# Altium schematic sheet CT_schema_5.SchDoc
size 578 x 363 mm
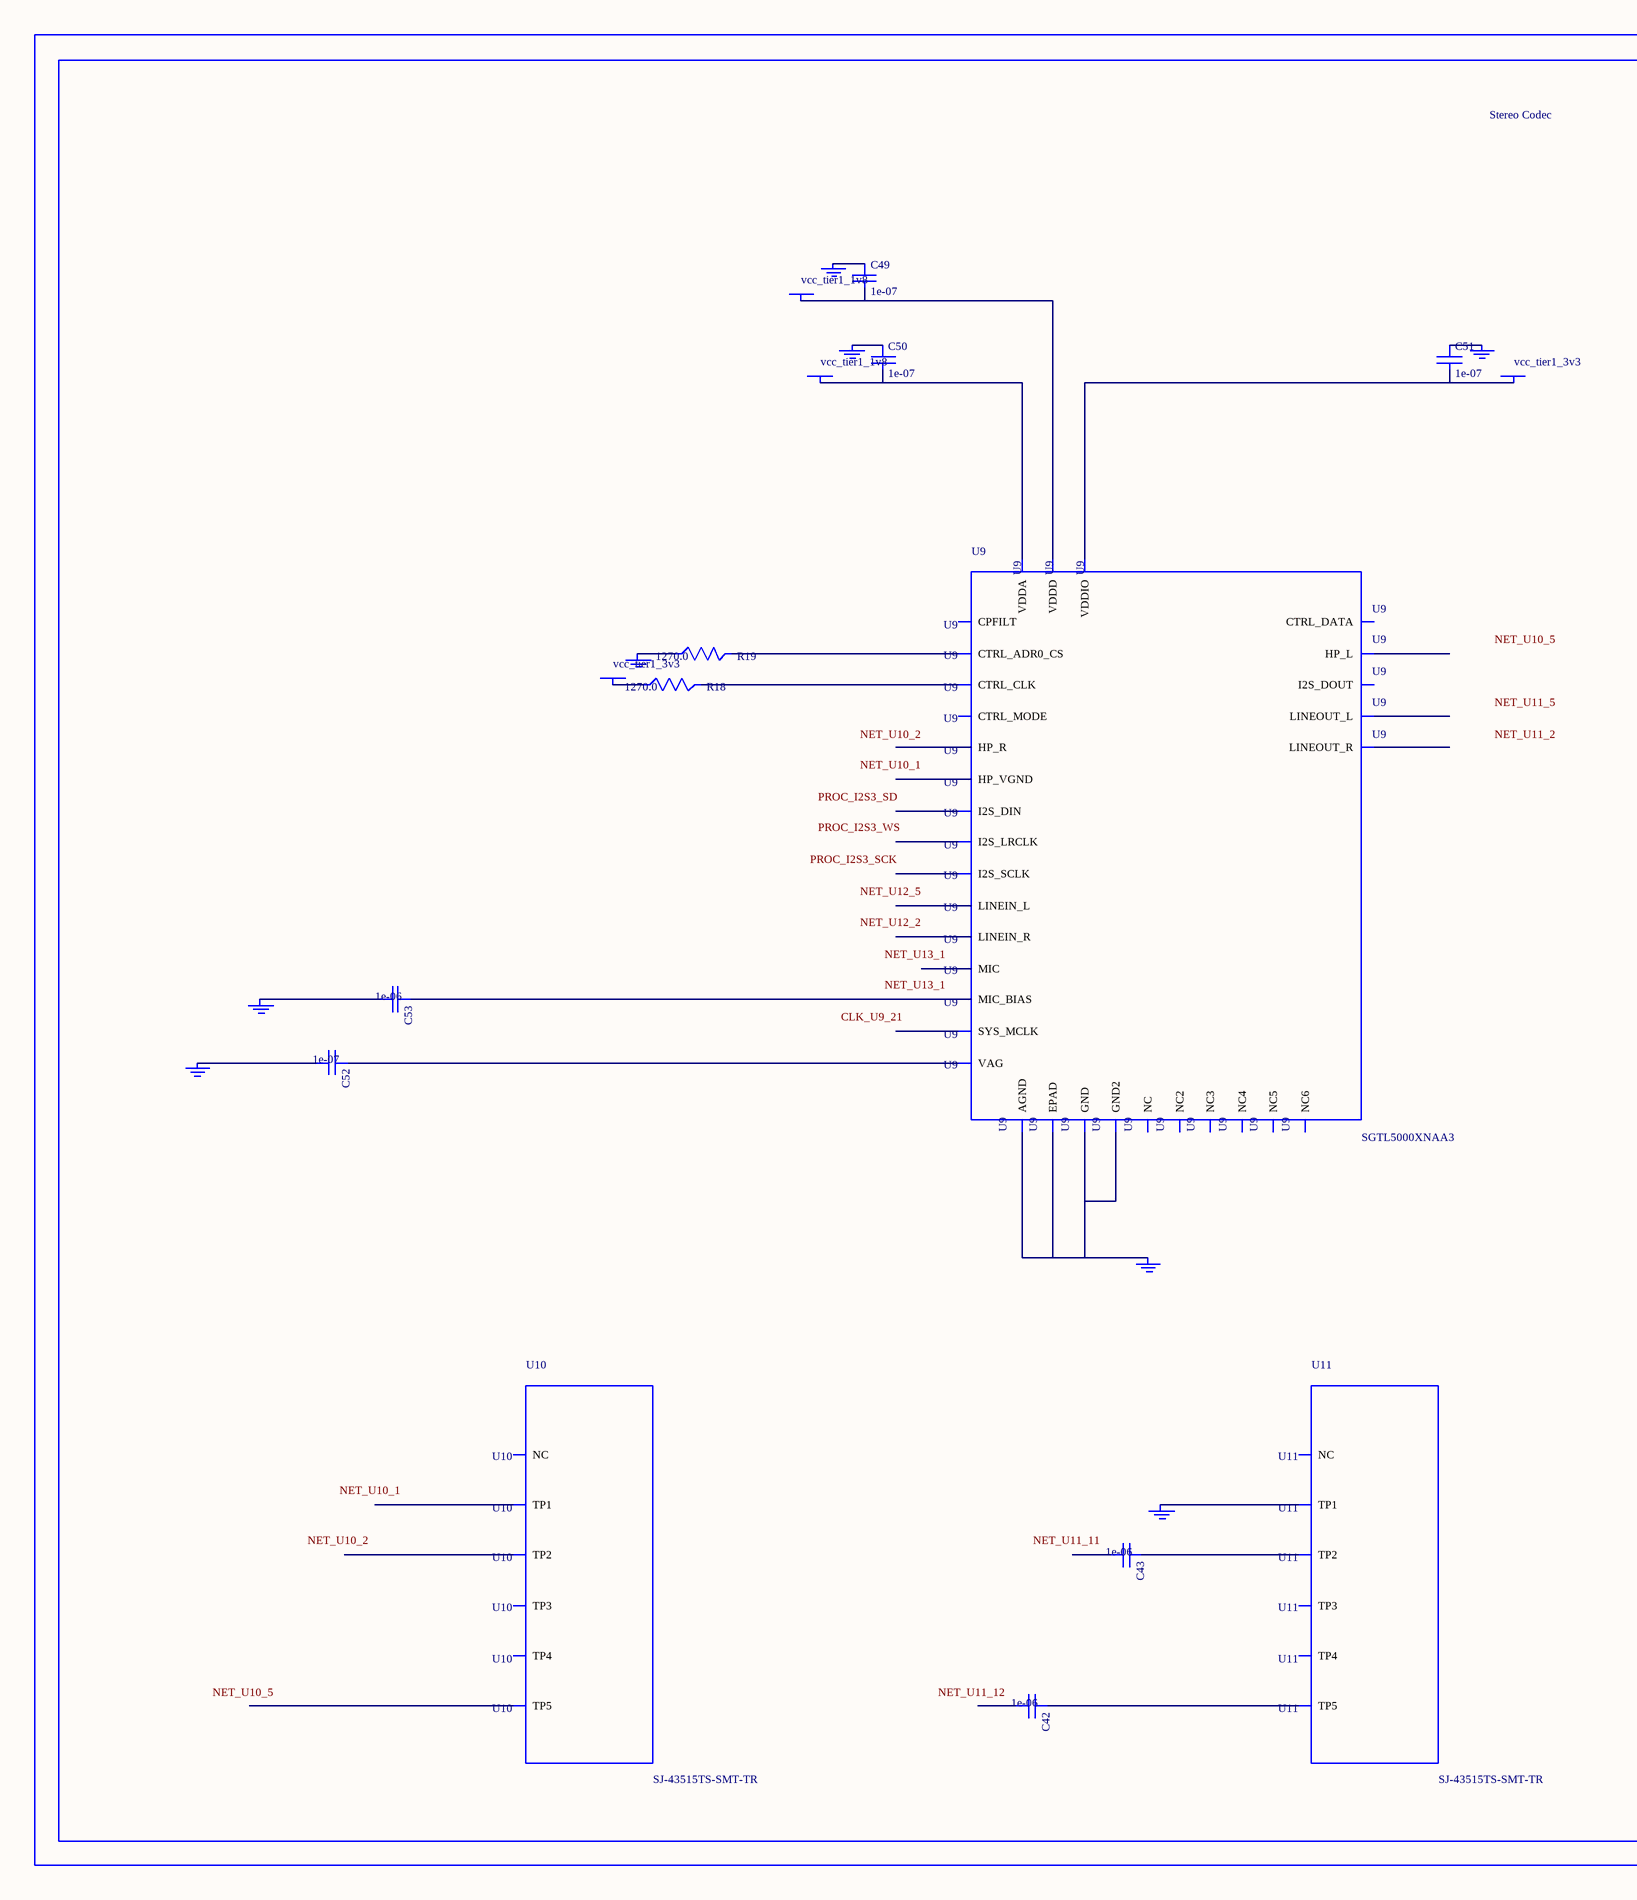
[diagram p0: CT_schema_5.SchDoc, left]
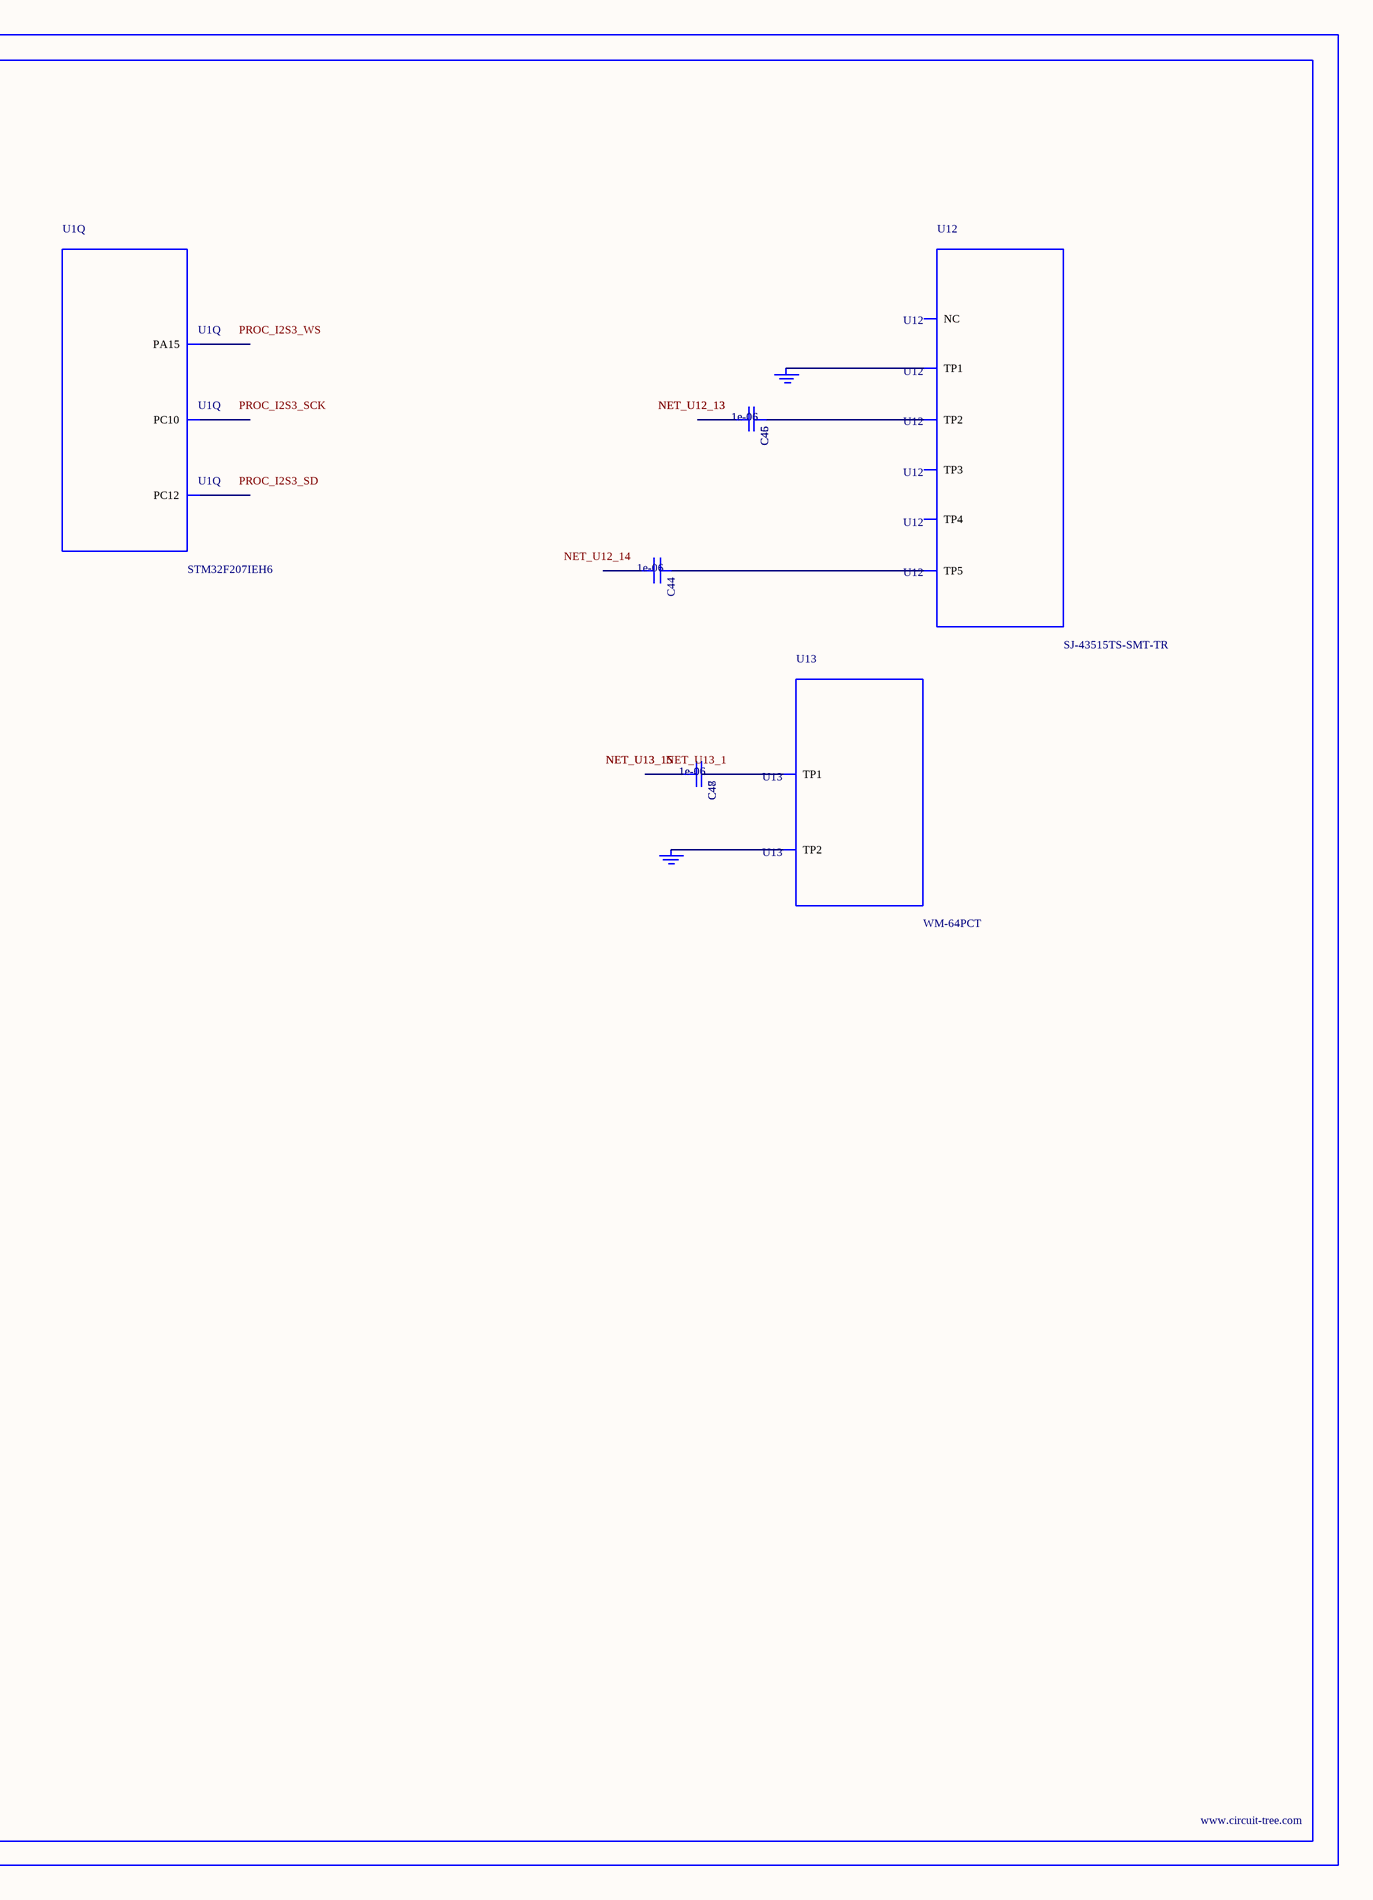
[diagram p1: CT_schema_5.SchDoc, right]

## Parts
BORDER4  (no value)
C42  1e-06  [C0603]
C43  1e-06  [C0603]
C44  1e-06  [C0603]
C45  1e-06  [C0603]
C46  1e-06  [C0603]
C47  1e-06  [C0603]
C48  1e-06  [C0603]
C49  1e-07  [C0402]
C50  1e-07  [C0402]
C51  1e-07  [C0402]
C52  1e-07  [C0402]
C53  1e-06  [C0603]
GND_INSTANCE_4_0  (no value)
GND_INSTANCE_4_1  (no value)
GND_INSTANCE_4_2  (no value)
GND_INSTANCE_4_3  (no value)
GND_INSTANCE_4_4  (no value)
GND_INSTANCE_4_5  (no value)
GND_INSTANCE_4_6  (no value)
GND_INSTANCE_4_7  (no value)
GND_INSTANCE_4_8  (no value)
GND_INSTANCE_4_9  (no value)
GND_INSTANCE_4_10  (no value)
POWER_INSTANCE_4_0  vcc_tier1_1v8
POWER_INSTANCE_4_1  vcc_tier1_3v3
POWER_INSTANCE_4_2  vcc_tier1_3v3
POWER_INSTANCE_4_3  vcc_tier1_1v8
R18  1270.0  [R0603]
R19  1270.0  [R0603]
U1  STM32F207IEH6  [UFBGA176_25]  (part Q of 18)
U9  SGTL5000XNAA3  [QFN-32]
U10  SJ-43515TS-SMT-TR  [SJ-43515TS-SMT-TR]
U11  SJ-43515TS-SMT-TR  [SJ-43515TS-SMT-TR]
U12  SJ-43515TS-SMT-TR  [SJ-43515TS-SMT-TR]
U13  WM-64PCT  [WM-64PC]

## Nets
NetC42_1: C42.1 U11.5(TP5)
NetC43_1: C43.1 U11.2(TP2)
NetC44_1: C44.1 U12.5(TP5)
NetC45_1: C45.1 C46.1 U12.2(TP2)
NetC45_2: C45.2 C46.2
NetC47_1: C47.1 C48.1 U13.1(TP1)
NetC47_2: C47.2 C48.2
NetC49_1: C49.1 GND_INSTANCE_4_5.0(GND)
NetC49_2: C49.2 POWER_INSTANCE_4_3.0(PWR) U9.30(VDDD)
NetC50_1: C50.1 GND_INSTANCE_4_1.0(GND)
NetC50_2: C50.2 POWER_INSTANCE_4_0.0(PWR) U9.5(VDDA)
NetC51_1: C51.1 GND_INSTANCE_4_4.0(GND)
NetC51_2: C51.2 POWER_INSTANCE_4_1.0(PWR) U9.20(VDDIO)
NetC52_1: C52.1 U9.10(VAG)
NetC52_2: C52.2 GND_INSTANCE_4_2.0(GND)
NetC53_1: C53.1 U9.16(MIC_BIAS)
NetC53_2: C53.2 GND_INSTANCE_4_3.0(GND)
NetGND_INSTANCE_4_0_0: GND_INSTANCE_4_0.0(GND) U9.1(GND) U9.3(GND2) U9.7(AGND) U9.EXP(EPAD)
NetGND_INSTANCE_4_6_0: GND_INSTANCE_4_6.0(GND) R19.1
NetGND_INSTANCE_4_7_0: GND_INSTANCE_4_7.0(GND) U11.1(TP1)
NetGND_INSTANCE_4_8_0: GND_INSTANCE_4_8.0(GND) GND_INSTANCE_4_9.0(GND) U12.1(TP1)
NetGND_INSTANCE_4_10_0: GND_INSTANCE_4_10.0(GND) U13.2(TP2)
NetPOWER_INSTANCE_4_2_0: POWER_INSTANCE_4_2.0(PWR) R18.1
NetR18_2: R18.2 U9.29(CTRL_CLK)
NetR19_2: R19.2 U9.31(CTRL_ADR0_CS)

Not connected (* = marked no-connect by the designer): C42 2; C43 2; C44 2; U1 A12(PC12) A13(PA15) B14(PC10); U9 2(HP_R) 4(HP_VGND) 6(HP_L) 8(NC) 9(NC2) 11(LINEOUT_R) 12(LINEOUT_L) 13(LINEIN_R) 14(LINEIN_L) 15(MIC) 17(NC3) 18(CPFILT) 19(NC4) 21(SYS_MCLK) 22(NC5) 23(I2S_LRCLK) 24(I2S_SCLK) 25(I2S_DOUT) 26(I2S_DIN) 27(CTRL_DATA) 28(NC6) 32(CTRL_MODE); U10 1(TP1) 2(TP2) 3(TP3) 4(TP4) 5(TP5) 6(NC); U11 3(TP3) 4(TP4) 6(NC); U12 3(TP3) 4(TP4) 6(NC)

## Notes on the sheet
- Labels drawn without touching a wire or pin: CLK_U9_21, NET_U10_1, NET_U10_2, NET_U10_5, NET_U11_2, NET_U11_5, NET_U11_11, NET_U11_12, NET_U12_2, NET_U12_5, NET_U12_14, NET_U13_1, PROC_I2S3_SCK, PROC_I2S3_SD, PROC_I2S3_WS

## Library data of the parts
BORDER4 = BORDER_PAGE4
C42-C48 C53 = C0603C105K3RACTU
C49-C52 = C0402C104K3RACTU
GND_INSTANCE_4_0-GND_INSTANCE_4_10 = GND
POWER_INSTANCE_4_0-POWER_INSTANCE_4_3 = PWR
R18 R19 = RC0603FR-071K27L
